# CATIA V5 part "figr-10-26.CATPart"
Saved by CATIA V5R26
Part number: Part1
Bounding box of the stored display mesh (mm): x -65.919 to 25.581, y -200.404 to 0.194, z 0 to 71.635
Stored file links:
  D:\_Deepak\CATIA\CATIA V5-6R2016_Deepak\Resources\Part files\Partfiles\c10_catia_v5_6r2016_prt\figr-10-26.CATPart
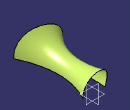
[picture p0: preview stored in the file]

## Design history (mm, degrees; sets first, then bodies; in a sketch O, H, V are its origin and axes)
Set1
  Sketch1 on xy-plane, origin (0, 0, 0), H (1, 0, 0), V (0, 1, 0)
    spline S1 through (-36.6295, 0) (-39.5961, -76.7629) (-56.6868, -154.7631) (-92.5015, -194.2587)
    point P1 (-36.6295, 0)
    coincidence: P1 H
  Sketch2 on xy-plane, origin (0, 0, 0), H (1, 0, 0), V (0, 1, 0)
    spline S1 through (25.5807, 0) (5.5021, -50.6307) (25.5807, -200.404)
    point P1 (25.5807, 0)
    coincidence: P1 H
  Sketch3 on zx-plane, origin (0, 0, 0), H (-1, 0, 0), V (0, 0, 1)
    spline S1 through (-25.5807, 0) (16.4189, 47.2175) (28.9802, 46.33) (36.6295, 0)
    reference projected point E1 (36.6295, 0) from vertex of Sketch1
    reference projected point E2 (-25.5807, 0) from vertex of Sketch2
    point P1 (-25.5807, 0)
    point P2 (36.6295, 0)
    coincidence: P1 H, P2 H, E1 P2, P1 E2
  Sweep1: type Unspec, Profile Sketch3, Guide (Sketch1; Sketch2), FittingPoints (vertex of Sketch1; vertex of Sketch2)
Body1 (main body)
